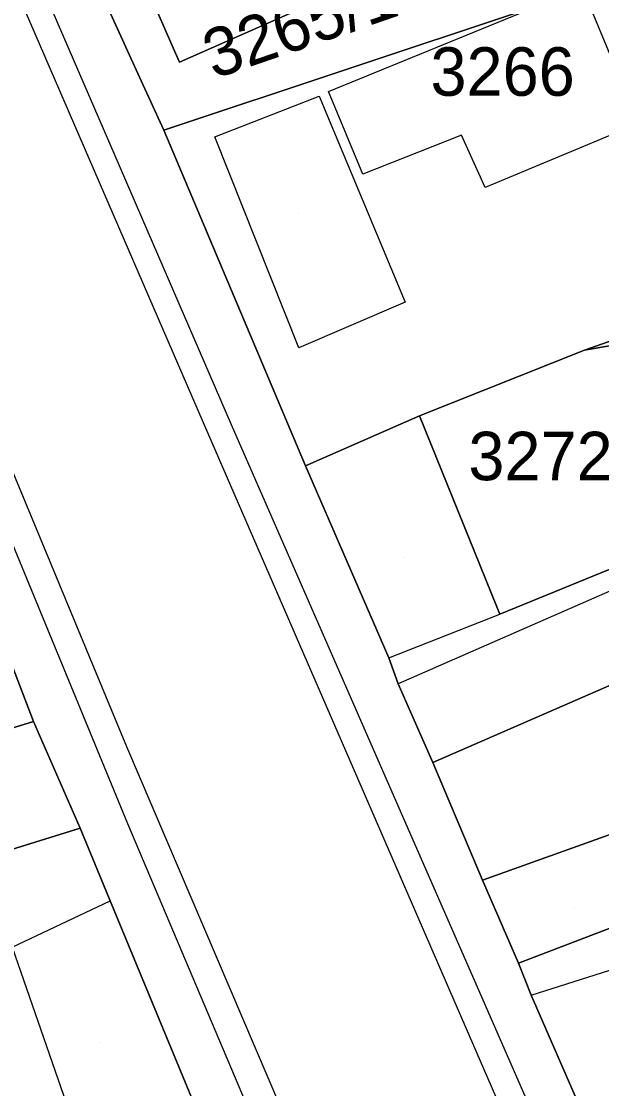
# Model space of a CAD drawing. Extents: x -262657 to -261595, y -1238015 to -1237156.
# Drawn here: x -261879.39 to -261855.46, y -1237897.37 to -1237853.34 of the extents above; entities that cross this region are included whole.
import ezdxf

# ---------------------------------------------------------------- set-up
doc = ezdxf.new("R2010")
doc.units = 0
for name, color, linetype in [('body_kn', 7, 'Continuous'), ('kladpar_druhypozemkov', 7, 'Continuous'), ('kladpar_hranice', 7, 'Continuous'), ('kladpar_parcelnecisla', 7, 'Continuous'), ('kladpar_plochy', 7, 'Continuous'), ('zappar_hrandruhpozemk', 7, 'Continuous')]:
    doc.layers.add(name, color=color, linetype=linetype)

msp = doc.modelspace()

# ---------------------------------------------------------------- linework, layer by layer
at = {"layer": 'body_kn'}
for p, q in [((-261872.88, -1237854.99), (-261872.88, -1237854.99)), ((-261872.87, -1237855.02), (-261872.87, -1237855.02)), ((-261872.87, -1237855.02), (-261872.87, -1237855.02)), ((-261874.52, -1237855.64), (-261874.52, -1237855.64)), ((-261866.72, -1237856.24), (-261866.72, -1237856.24)), ((-261866.72, -1237856.24), (-261866.72, -1237856.24)), ((-261867.11, -1237856.43), (-261867.11, -1237856.43)), ((-261873.52, -1237857.83), (-261873.52, -1237857.83)), ((-261873.52, -1237857.83), (-261873.52, -1237857.83)), ((-261861.24, -1237858.04), (-261861.24, -1237858.04)), ((-261871.41, -1237858.11), (-261871.41, -1237858.11)), ((-261871.41, -1237858.11), (-261871.41, -1237858.11)), ((-261865.31, -1237859.65), (-261865.31, -1237859.65)), ((-261860.27, -1237860.19), (-261860.27, -1237860.19)), ((-261863.56, -1237864.92), (-261863.56, -1237864.92)), ((-261867.95, -1237866.81), (-261867.95, -1237866.81)), ((-261856.17, -1237866.91), (-261856.17, -1237866.91)), ((-261870.74, -1237869.97), (-261870.74, -1237869.97)), ((-261862.97, -1237869.61), (-261862.97, -1237869.61)), ((-261871.7, -1237870.32), (-261871.7, -1237870.32)), ((-261867.67, -1237871.68), (-261867.67, -1237871.68)), ((-261867.67, -1237871.68), (-261867.67, -1237871.68)), ((-261859.78, -1237877.5), (-261859.78, -1237877.5)), ((-261859.66, -1237877.79), (-261859.66, -1237877.79)), ((-261864.24, -1237879.6), (-261864.24, -1237879.6)), ((-261864.24, -1237879.6), (-261864.24, -1237879.6)), ((-261863.85, -1237880.67), (-261863.85, -1237880.67)), ((-261878.89, -1237882.22), (-261878.89, -1237882.22)), ((-261875.05, -1237883.26), (-261875.05, -1237883.26)), ((-261862.42, -1237883.92), (-261862.42, -1237883.92)), ((-261876.97, -1237886.62), (-261876.97, -1237886.62)), ((-261876.97, -1237886.62), (-261876.97, -1237886.62)), ((-261875, -1237886.44), (-261875, -1237886.44)), ((-261860.37, -1237888.77), (-261860.37, -1237888.77)), ((-261875.73, -1237889.62), (-261875.73, -1237889.62)), ((-261858.89, -1237892.19), (-261858.89, -1237892.19)), ((-261858.36, -1237893.51), (-261858.36, -1237893.51)), ((-261858.36, -1237893.51), (-261858.36, -1237893.51))]:
    msp.add_line(p, q, dxfattribs=at)
at = {"layer": 'kladpar_druhypozemkov'}
for p, q in [((-261858.57, -1237854.23), (-261858.57, -1237854.23)), ((-261867.96, -1237861.28), (-261867.96, -1237861.28)), ((-261863.6, -1237875.44), (-261863.6, -1237875.44)), ((-261856.59, -1237889.94), (-261856.59, -1237889.94)), ((-261876.18, -1237895.45), (-261876.18, -1237895.45))]:
    msp.add_line(p, q, dxfattribs=at)
at = {"layer": 'kladpar_hranice'}
for points in [[(-261897.39, -1237804.1), (-261892.46, -1237815.38), (-261890.38, -1237820.3), (-261888.53, -1237824.53), (-261885.29, -1237831.79), (-261884.38, -1237833.72), (-261884, -1237834.66), (-261881.91, -1237839.28), (-261881.21, -1237840.86), (-261879.01, -1237845.76), (-261874.52, -1237855.64), (-261873.52, -1237857.83), (-261867.67, -1237871.68), (-261864.24, -1237879.6), (-261863.85, -1237880.67), (-261862.42, -1237883.92), (-261860.37, -1237888.77), (-261858.89, -1237892.19), (-261858.36, -1237893.51), (-261854.78, -1237901.75)], [(-261867.89, -1237908.17), (-261869.84, -1237903.85), (-261871.28, -1237900.38), (-261871.81, -1237899.1), (-261875.73, -1237889.62), (-261876.97, -1237886.62), (-261878.89, -1237882.22), (-261879.83, -1237879.78), (-261882.36, -1237872.9), (-261884.52, -1237867.46), (-261886.78, -1237861.7), (-261887.83, -1237859.39), (-261891.38, -1237851.58), (-261896.16, -1237839.29), (-261898.28, -1237834.11), (-261898.91, -1237832.53), (-261900.73, -1237828.11), (-261906.4, -1237814.7), (-261906.69, -1237814.03), (-261914.09, -1237816.76)], [(-261872.87, -1237855.02), (-261872.88, -1237854.99), (-261875.3, -1237849.47), (-261875.16, -1237849.41), (-261877.05, -1237845.08), (-261876.67, -1237844.94), (-261874.95, -1237844.35), (-261874.53, -1237844.2), (-261869.68, -1237842.51), (-261864.15, -1237840.59), (-261863.99, -1237840.95), (-261862.14, -1237845.2), (-261862.02, -1237845.47), (-261864.78, -1237846.7), (-261863.83, -1237848.85), (-261865.95, -1237849.78), (-261865.14, -1237851.6), (-261872.87, -1237855.02)], [(-261873.52, -1237857.83), (-261874.52, -1237855.64), (-261879.01, -1237845.76), (-261877.05, -1237845.08), (-261875.16, -1237849.41), (-261875.3, -1237849.47), (-261872.88, -1237854.99), (-261872.87, -1237855.02), (-261865.14, -1237851.6), (-261865.95, -1237849.78), (-261863.83, -1237848.85), (-261864.78, -1237846.7), (-261862.02, -1237845.47), (-261862.14, -1237845.2), (-261861.86, -1237845.07), (-261858.52, -1237852.84), (-261873.52, -1237857.83)], [(-261867.67, -1237871.68), (-261873.52, -1237857.83), (-261858.52, -1237852.84), (-261856.26, -1237851.95), (-261849.86, -1237849.49), (-261844.94, -1237862.93), (-261846.62, -1237863.53), (-261856.17, -1237866.91), (-261862.97, -1237869.61), (-261867.67, -1237871.68)], [(-261836.71, -1237880.35), (-261842.22, -1237882.31), (-261843.24, -1237882.64), (-261845.79, -1237876.67), (-261862.42, -1237883.92), (-261863.85, -1237880.67), (-261864.24, -1237879.6), (-261867.67, -1237871.68), (-261862.97, -1237869.61), (-261859.78, -1237877.5), (-261859.66, -1237877.79), (-261852.89, -1237875.03), (-261848.86, -1237873.39), (-261849.71, -1237871.29), (-261845.57, -1237869.61), (-261847.66, -1237864.45), (-261851.85, -1237866.15), (-261856.17, -1237866.91), (-261846.62, -1237863.53), (-261836.71, -1237880.35)], [(-261851.85, -1237866.15), (-261849.71, -1237871.29), (-261848.86, -1237873.39), (-261852.89, -1237875.03), (-261859.66, -1237877.79), (-261859.78, -1237877.5), (-261862.97, -1237869.61), (-261856.17, -1237866.91), (-261851.85, -1237866.15)], [(-261882.36, -1237872.9), (-261879.83, -1237879.78), (-261878.89, -1237882.22), (-261894.18, -1237886.93), (-261898.78, -1237878.61), (-261886.24, -1237874.19), (-261882.36, -1237872.9)], [(-261843.24, -1237882.64), (-261860.37, -1237888.77), (-261862.42, -1237883.92), (-261845.79, -1237876.67), (-261843.24, -1237882.64)], [(-261898.78, -1237878.61), (-261894.18, -1237886.93), (-261878.89, -1237882.22), (-261876.97, -1237886.62), (-261894.62, -1237892.11), (-261907.78, -1237896.04), (-261908.12, -1237895.91), (-261908.99, -1237895.57), (-261911.99, -1237882.98), (-261906.43, -1237881.14), (-261898.78, -1237878.61)], [(-261842.22, -1237882.31), (-261836.71, -1237895.38), (-261844.34, -1237898.1), (-261850.59, -1237900.3), (-261854.78, -1237901.75), (-261858.36, -1237893.51), (-261858.89, -1237892.19), (-261841.92, -1237885.7), (-261843.24, -1237882.64), (-261842.22, -1237882.31)], [(-261843.24, -1237882.64), (-261841.92, -1237885.7), (-261858.89, -1237892.19), (-261860.37, -1237888.77), (-261843.24, -1237882.64)], [(-261876.97, -1237886.62), (-261875.73, -1237889.62), (-261871.81, -1237899.1), (-261871.28, -1237900.38), (-261888.58, -1237907.33), (-261894.62, -1237892.11), (-261876.97, -1237886.62)]]:
    msp.add_lwpolyline(points, dxfattribs=at)
at = {"layer": 'kladpar_plochy'}
for points in [[(-261897.39, -1237804.1), (-261892.46, -1237815.38), (-261890.38, -1237820.3), (-261888.53, -1237824.53), (-261885.29, -1237831.79), (-261884.38, -1237833.72), (-261884, -1237834.66), (-261881.91, -1237839.28), (-261881.21, -1237840.86), (-261879.01, -1237845.76), (-261874.52, -1237855.64), (-261873.52, -1237857.83), (-261867.67, -1237871.68), (-261864.24, -1237879.6), (-261863.85, -1237880.67), (-261862.42, -1237883.92), (-261860.37, -1237888.77), (-261858.89, -1237892.19), (-261858.36, -1237893.51), (-261854.78, -1237901.75)], [(-261871.81, -1237899.1), (-261875.73, -1237889.62), (-261876.97, -1237886.62), (-261878.89, -1237882.22), (-261879.83, -1237879.78), (-261882.36, -1237872.9), (-261884.52, -1237867.46), (-261886.78, -1237861.7), (-261887.83, -1237859.39), (-261891.38, -1237851.58), (-261896.16, -1237839.29), (-261898.28, -1237834.11), (-261898.91, -1237832.53), (-261900.73, -1237828.11), (-261906.4, -1237814.7), (-261906.69, -1237814.03), (-261914.09, -1237816.76), (-261923.62, -1237819.21), (-261923.89, -1237818.34), (-261924, -1237817.96), (-261923.67, -1237817.87), (-261913.97, -1237813.57)]]:
    msp.add_lwpolyline(points, dxfattribs=at)
for points in [[(-261872.87, -1237855.02), (-261872.88, -1237854.99), (-261875.3, -1237849.47), (-261875.16, -1237849.41), (-261877.05, -1237845.08), (-261876.67, -1237844.94), (-261874.95, -1237844.35), (-261874.53, -1237844.2), (-261869.68, -1237842.51), (-261864.15, -1237840.59), (-261863.99, -1237840.95), (-261862.14, -1237845.2), (-261862.02, -1237845.47), (-261864.78, -1237846.7), (-261863.83, -1237848.85), (-261865.95, -1237849.78), (-261865.14, -1237851.6)], [(-261873.52, -1237857.83), (-261874.52, -1237855.64), (-261879.01, -1237845.76), (-261877.05, -1237845.08), (-261875.16, -1237849.41), (-261875.3, -1237849.47), (-261872.88, -1237854.99), (-261872.87, -1237855.02), (-261865.14, -1237851.6), (-261865.95, -1237849.78), (-261863.83, -1237848.85), (-261864.78, -1237846.7), (-261862.02, -1237845.47), (-261862.14, -1237845.2), (-261861.86, -1237845.07), (-261858.52, -1237852.84)], [(-261867.67, -1237871.68), (-261873.52, -1237857.83), (-261858.52, -1237852.84), (-261856.26, -1237851.95), (-261849.86, -1237849.49), (-261844.94, -1237862.93), (-261846.62, -1237863.53), (-261856.17, -1237866.91), (-261862.97, -1237869.61)], [(-261836.71, -1237880.35), (-261842.22, -1237882.31), (-261843.24, -1237882.64), (-261845.79, -1237876.67), (-261862.42, -1237883.92), (-261863.85, -1237880.67), (-261864.24, -1237879.6), (-261867.67, -1237871.68), (-261862.97, -1237869.61), (-261859.78, -1237877.5), (-261859.66, -1237877.79), (-261852.89, -1237875.03), (-261848.86, -1237873.39), (-261849.71, -1237871.29), (-261845.57, -1237869.61), (-261847.66, -1237864.45), (-261851.85, -1237866.15), (-261856.17, -1237866.91), (-261846.62, -1237863.53)], [(-261851.85, -1237866.15), (-261849.71, -1237871.29), (-261848.86, -1237873.39), (-261852.89, -1237875.03), (-261859.66, -1237877.79), (-261859.78, -1237877.5), (-261862.97, -1237869.61), (-261856.17, -1237866.91)], [(-261882.36, -1237872.9), (-261879.83, -1237879.78), (-261878.89, -1237882.22), (-261894.18, -1237886.93), (-261898.78, -1237878.61), (-261886.24, -1237874.19)], [(-261843.24, -1237882.64), (-261860.37, -1237888.77), (-261862.42, -1237883.92), (-261845.79, -1237876.67)], [(-261898.78, -1237878.61), (-261894.18, -1237886.93), (-261878.89, -1237882.22), (-261876.97, -1237886.62), (-261894.62, -1237892.11), (-261907.78, -1237896.04), (-261908.12, -1237895.91), (-261908.99, -1237895.57), (-261911.99, -1237882.98), (-261906.43, -1237881.14)], [(-261842.22, -1237882.31), (-261836.71, -1237895.38), (-261844.34, -1237898.1), (-261850.59, -1237900.3), (-261854.78, -1237901.75), (-261858.36, -1237893.51), (-261858.89, -1237892.19), (-261841.92, -1237885.7), (-261843.24, -1237882.64)], [(-261843.24, -1237882.64), (-261841.92, -1237885.7), (-261858.89, -1237892.19), (-261860.37, -1237888.77)], [(-261876.97, -1237886.62), (-261875.73, -1237889.62), (-261871.81, -1237899.1), (-261871.28, -1237900.38), (-261888.58, -1237907.33), (-261894.62, -1237892.11)]]:
    msp.add_lwpolyline(points, close=True, dxfattribs=at)
at = {"layer": 'zappar_hrandruhpozemk'}
for p, q in [((-261924.51, -1237745.6), (-261870.74, -1237869.97)), ((-261853.94, -1237857.55), (-261860.27, -1237860.19)), ((-261867.95, -1237866.81), (-261871.41, -1237858.11)), ((-261863.56, -1237864.92), (-261867.95, -1237866.81)), ((-261852.58, -1237875.73), (-261863.85, -1237880.67)), ((-261864.24, -1237879.6), (-261859.66, -1237877.79)), ((-261866.13, -1237907.4), (-261875, -1237886.44)), ((-261879.77, -1237891.53), (-261875.73, -1237889.62))]:
    msp.add_line(p, q, dxfattribs=at)
for points in [[(-261857.29, -1237903.53), (-261871.7, -1237870.32), (-261925.44, -1237746.09), (-261934.35, -1237714.96)], [(-261875, -1237886.44), (-261927.55, -1237758.77), (-261932.46, -1237746.83)], [(-261917.3, -1237781.31), (-261875.05, -1237883.26), (-261864.96, -1237906.9)], [(-261866.72, -1237856.24), (-261856.26, -1237851.95), (-261853.94, -1237857.55)], [(-261860.27, -1237860.19), (-261861.24, -1237858.04), (-261865.31, -1237859.65), (-261866.72, -1237856.24)], [(-261871.41, -1237858.11), (-261867.11, -1237856.43), (-261863.56, -1237864.92)], [(-261870.74, -1237869.97), (-261844.45, -1237930.08), (-261844.5, -1237930.1)], [(-261858.36, -1237893.51), (-261853.65, -1237892.02), (-261847.61, -1237889.67)], [(-261879.77, -1237891.53), (-261876.47, -1237901.05), (-261885.37, -1237904.78), (-261888.19, -1237905.96)]]:
    msp.add_lwpolyline(points, dxfattribs=at)

# ---------------------------------------------------------------- texts
at = {"layer": 'kladpar_parcelnecisla'}
msp.add_text('3265/1', height=2, rotation=19, dxfattribs=at).set_placement((-261871.454, -1237855.731))
for s, p in [('3266', (-261862.519, -1237856.41)), ('3272/2', (-261860.955, -1237872.27))]:
    msp.add_text(s, height=2, dxfattribs=at).set_placement(p)

doc.saveas('drawing.dxf')
